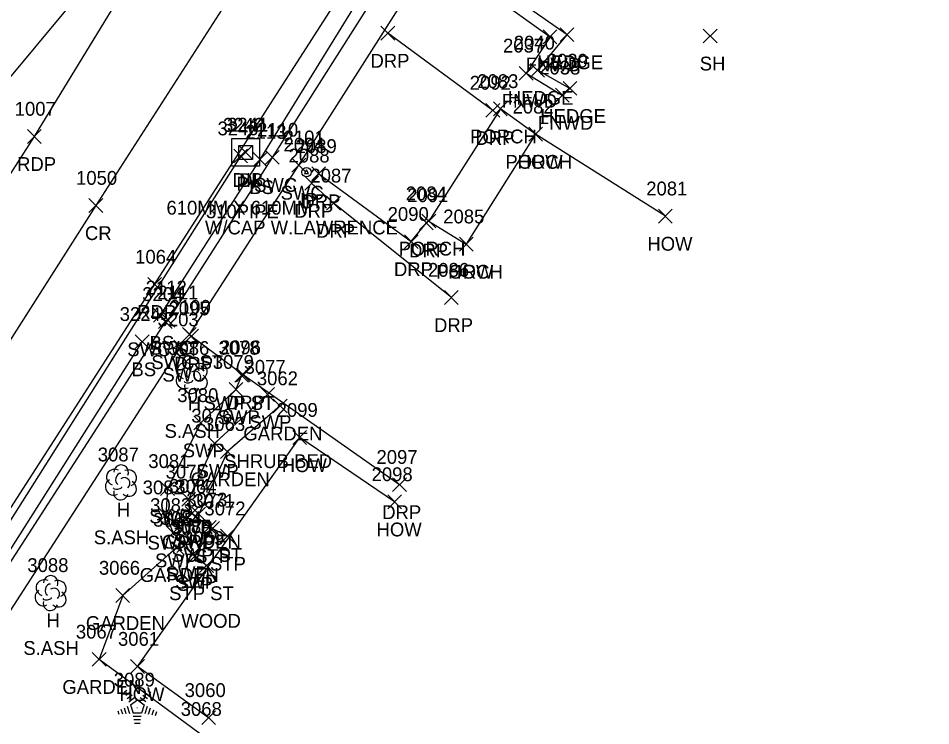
# Model space of a CAD drawing. Extents: x 1634209 to 1639641, y 608564 to 612258.
# Drawn here: x 1639021.2 to 1639153.3, y 611048.4 to 611150.8 of the extents above; entities that cross this region are included whole.
import ezdxf

# ---------------------------------------------------------------- set-up
doc = ezdxf.new("R2010")
doc.units = 0
for name, color, linetype in [('D_A', 7, 'Continuous'), ('D_C', 7, 'Continuous'), ('D_I', 7, 'Continuous'), ('D_TIC', 7, 'Continuous'), ('DCP', 7, 'Continuous'), ('DS', 7, 'Continuous'), ('L_A', 7, 'Continuous'), ('L_C', 7, 'Continuous'), ('L_I', 7, 'Continuous'), ('L_TIC', 7, 'Continuous'), ('LAHR', 7, 'Continuous'), ('LAPB', 7, 'Continuous'), ('LBC', 7, 'Continuous'), ('LBF', 7, 'Continuous'), ('LELB', 7, 'Continuous'), ('LFNC', 7, 'Continuous'), ('LTC', 7, 'Continuous'), ('LTD', 7, 'Continuous'), ('M_A', 7, 'Continuous'), ('M_C', 7, 'Continuous'), ('M_I', 7, 'Continuous'), ('MPIR', 7, 'Continuous'), ('P_A', 7, 'Continuous'), ('P_I', 7, 'Continuous'), ('P_TIC', 7, 'Continuous'), ('PET', 7, 'Continuous'), ('PRC', 7, 'Continuous'), ('R_A', 7, 'Continuous'), ('R_I', 7, 'Continuous'), ('R_TIC', 7, 'Continuous'), ('RDP', 7, 'Continuous'), ('RSW', 7, 'Continuous')]:
    doc.layers.add(name, color=color, linetype=linetype)

msp = doc.modelspace()

# ---------------------------------------------------------------- linework, layer by layer
at = {"layer": 'D_TIC'}
for points in [[(1639052.43, 611129.86), (1639054.43, 611131.86)], [(1639054.43, 611129.86), (1639052.43, 611131.86)], [(1639053.15, 611130.4), (1639055.15, 611132.4)], [(1639055.15, 611130.4), (1639053.15, 611132.4)]]:
    msp.add_lwpolyline(points, dxfattribs=at)
at = {"layer": 'DCP'}
msp.add_lwpolyline([(1638981.5, 611017.05), (1639053.43, 611130.86)], dxfattribs=at)
at = {"layer": 'DS'}
for p, q in [((1639052.14, 611133.38), (1639056.14, 611133.38)), ((1639052.14, 611129.38), (1639052.14, 611133.38)), ((1639056.14, 611133.38), (1639056.14, 611129.38)), ((1639053.14, 611130.38), (1639053.14, 611132.38)), ((1639053.14, 611132.38), (1639055.14, 611132.38)), ((1639055.14, 611132.38), (1639055.14, 611130.38)), ((1639055.14, 611130.38), (1639053.14, 611130.38)), ((1639054.14, 611131.38), (1639054.14, 611131.38)), ((1639054.14, 611131.38), (1639054.14, 611131.38)), ((1639056.14, 611129.38), (1639052.14, 611129.38))]:
    msp.add_line(p, q, dxfattribs=at)
at = {"layer": 'L_TIC'}
for points in [[(1639097.22, 611147.12), (1639099.22, 611149.12)], [(1639099.22, 611147.12), (1639097.22, 611149.12)], [(1639099.68, 611147.43), (1639101.68, 611149.43)], [(1639101.68, 611147.43), (1639099.68, 611149.43)], [(1639120.39, 611147.25), (1639122.39, 611149.25)], [(1639122.39, 611147.25), (1639120.39, 611149.25)], [(1639093.75, 611141.85), (1639095.75, 611143.85)], [(1639095.75, 611141.85), (1639093.75, 611143.85)], [(1639095.39, 611142.28), (1639097.39, 611144.28)], [(1639097.39, 611142.28), (1639095.39, 611144.28)], [(1639100.1, 611139.66), (1639102.1, 611141.66)], [(1639102.1, 611139.66), (1639100.1, 611141.66)], [(1639098.99, 611138.67), (1639100.99, 611140.67)], [(1639100.99, 611138.67), (1639098.99, 611140.67)], [(1639090.02, 611136.7), (1639092.02, 611138.7)], [(1639092.02, 611136.7), (1639090.02, 611138.7)], [(1639095.13, 611133.02), (1639097.13, 611135.02)], [(1639097.13, 611133.02), (1639095.13, 611135.02)], [(1639095.13, 611133.02), (1639097.13, 611135.02)], [(1639097.13, 611133.02), (1639095.13, 611135.02)], [(1639055.24, 611129.36), (1639057.24, 611131.36)], [(1639057.24, 611129.36), (1639055.24, 611131.36)], [(1639079.67, 611120.45), (1639081.67, 611122.45)], [(1639081.67, 611120.45), (1639079.67, 611122.45)], [(1639113.91, 611121.16), (1639115.91, 611123.16)], [(1639115.91, 611121.16), (1639113.91, 611123.16)], [(1639085.09, 611117.11), (1639087.09, 611119.11)], [(1639087.09, 611117.11), (1639085.09, 611119.11)], [(1639085.09, 611117.11), (1639087.09, 611119.11)], [(1639087.09, 611117.11), (1639085.09, 611119.11)], [(1639040.81, 611106.81), (1639042.81, 611108.81)], [(1639042.81, 611106.81), (1639040.81, 611108.81)], [(1639038.18, 611102.98), (1639040.18, 611104.98)], [(1639040.18, 611102.98), (1639038.18, 611104.98)], [(1639058.15, 611093.68), (1639060.15, 611095.68)], [(1639060.15, 611093.68), (1639058.15, 611095.68)], [(1639060.98, 611089.1), (1639062.98, 611091.1)], [(1639062.98, 611089.1), (1639060.98, 611091.1)], [(1639050.52, 611087.06), (1639052.52, 611089.06)], [(1639052.52, 611087.06), (1639050.52, 611089.06)], [(1639074.72, 611079.79), (1639076.72, 611081.79)], [(1639076.72, 611079.79), (1639074.72, 611081.79)], [(1639046.36, 611078.02), (1639048.36, 611080.02)], [(1639048.36, 611078.02), (1639046.36, 611080.02)], [(1639048.37, 611075.93), (1639050.37, 611077.93)], [(1639050.37, 611075.93), (1639048.37, 611077.93)], [(1639050.52, 611074.83), (1639052.52, 611076.83)], [(1639052.52, 611074.83), (1639050.52, 611076.83)], [(1639043.15, 611073.2), (1639045.15, 611075.2)], [(1639045.15, 611073.2), (1639043.15, 611075.2)], [(1639045.76, 611071.91), (1639047.76, 611073.91)], [(1639047.76, 611071.91), (1639045.76, 611073.91)], [(1639047.48, 611070.56), (1639049.48, 611072.56)], [(1639049.48, 611070.56), (1639047.48, 611072.56)], [(1639035.35, 611066.24), (1639037.35, 611068.24)], [(1639037.35, 611066.24), (1639035.35, 611068.24)], [(1639031.95, 611056.99), (1639033.95, 611058.99)], [(1639033.95, 611056.99), (1639031.95, 611058.99)], [(1639037.49, 611055.95), (1639039.49, 611057.95)], [(1639039.49, 611055.95), (1639037.49, 611057.95)], [(1639047.79, 611048.53), (1639049.79, 611050.53)], [(1639049.79, 611048.53), (1639047.79, 611050.53)]]:
    msp.add_lwpolyline(points, dxfattribs=at)
at = {"layer": 'LAHR'}
msp.add_lwpolyline([(1639101.1, 611140.66), (1639096.39, 611143.28), (1639100.68, 611148.43), (1639084.75, 611159.57), (1639110.62, 611199.46)], dxfattribs=at)
at = {"layer": 'LAPB'}
for points in [[(1639059.15, 611094.68), (1639051.52, 611088.06), (1639047.36, 611079.02)], [(1639044.15, 611074.2), (1639036.35, 611067.24), (1639032.95, 611057.99), (1639048.14, 611046.8)]]:
    msp.add_lwpolyline(points, dxfattribs=at)
at = {"layer": 'LBC'}
for points in [[(1639114.91, 611122.16), (1639096.13, 611134.02), (1639086.09, 611118.11)], [(1639038.49, 611056.95), (1639061.98, 611090.1)], [(1639075.72, 611080.79), (1639061.98, 611090.1)], [(1639048.79, 611049.53), (1639038.49, 611056.95)]]:
    msp.add_lwpolyline(points, dxfattribs=at)
at = {"layer": 'LBF'}
for points in [[(1639096.13, 611134.02), (1639091.02, 611137.7), (1639080.67, 611121.45), (1639086.09, 611118.11)], [(1639048.48, 611071.56), (1639046.76, 611072.91), (1639049.37, 611076.93), (1639051.52, 611075.83)]]:
    msp.add_lwpolyline(points, dxfattribs=at)
at = {"layer": 'LELB'}
for points in [[(1639041.81, 611107.81), (1639056.24, 611130.36), (1639075.11, 611161), (1639098.5, 611197.47), (1639122.91, 611234.07), (1639126.22, 611237.88)], [(1638966.07, 611052.28), (1638973.12, 611062.49), (1638979.47, 611078.29), (1638990.68, 611098.4), (1639000.87, 611114.56), (1639014.69, 611135.84), (1639038.15, 611164.03), (1639040.42, 611167.6)], [(1638982.99, 611014.59), (1639013.75, 611063.89), (1639039.18, 611103.98)]]:
    msp.add_lwpolyline(points, dxfattribs=at)
at = {"layer": 'LFNC'}
msp.add_lwpolyline([(1639109.56, 611199.9), (1639082.52, 611159.43), (1639098.22, 611148.12), (1639094.75, 611142.85), (1639099.99, 611139.67)], dxfattribs=at)
at = {"layer": 'LTC'}
for p, q in [((1639036.6, 611053.26), (1639036.96, 611053.52)), ((1639036.81, 611052.79), (1639037.34, 611053.18)), ((1639037.02, 611052.33), (1639037.73, 611052.84)), ((1639037.23, 611051.86), (1639038.11, 611052.5)), ((1639038.89, 611052.46), (1639039.7, 611051.87)), ((1639039.26, 611052.8), (1639039.94, 611052.31)), ((1639039.63, 611053.15), (1639040.18, 611052.75)), ((1639040, 611053.5), (1639040.42, 611053.2)), ((1639037, 611051.19), (1639037.33, 611050.17)), ((1639037.46, 611051.41), (1639038.47, 611052.14)), ((1639037.46, 611051.41), (1639037.85, 611050.21)), ((1639038.47, 611052.14), (1639039.47, 611051.42)), ((1639039.47, 611051.42), (1639039.08, 611050.21)), ((1639039.9, 611051.15), (1639039.57, 611050.11)), ((1639035.64, 611050.54), (1639035.79, 611050.07)), ((1639036.09, 611050.76), (1639036.3, 611050.1)), ((1639036.55, 611050.97), (1639036.82, 611050.14)), ((1639039.08, 611050.21), (1639037.85, 611050.21)), ((1639040.35, 611050.9), (1639040.06, 611050.01)), ((1639040.79, 611050.65), (1639040.56, 611049.92)), ((1639041.24, 611050.4), (1639041.05, 611049.82)), ((1639039.04, 611049.71), (1639037.89, 611049.71)), ((1639038.95, 611049.21), (1639037.97, 611049.21)), ((1639038.87, 611048.71), (1639038.04, 611048.71))]:
    msp.add_line(p, q, dxfattribs=at)
at = {"layer": 'LTD'}
for p, q in [((1639046.33, 611099.06), (1639046.33, 611099.06)), ((1639046.33, 611099.06), (1639046.33, 611099.06)), ((1639036.08, 611083.65), (1639036.08, 611083.65)), ((1639036.08, 611083.65), (1639036.08, 611083.65)), ((1639025.89, 611067.63), (1639025.89, 611067.63)), ((1639025.89, 611067.63), (1639025.89, 611067.63))]:
    msp.add_line(p, q, dxfattribs=at)
for centre in [(1639046.38, 611100.5), (1639036.13, 611085.09), (1639025.94, 611069.06)]:
    msp.add_arc(centre, 1.05, 335.5272, 180.9563, dxfattribs=at)
for centre, major_axis, ratio, start_param, end_param in [((1639045.54, 611099.73), (1.21, -0.51), 0.895232, 1.570796, 4.712389), ((1639046.12, 611099.52), (-0.208, -0.792), 0.645439, 3.141593, 6.283185), ((1639047.37, 611099.65), (-1.14, -0.48), 0.949671, 1.570796, 4.712389), ((1639045.25, 611098.36), (0.58, -1.04), 0.959034, 3.141593, 6.283185), ((1639046.83, 611098.9), (-0.5, 0.667), 0.989748, 3.141593, 6.283185), ((1639047.33, 611098.23), (-1.09, 0.79), 0.841452, 1.570796, 4.712389), ((1639046.33, 611097.56), (0.26, 1.06), 0.942809, 1.570796, 4.712389), ((1639045.87, 611098.31), (-0.625, -0.083), 0.423636, 0, 3.141593), ((1639035.29, 611084.32), (1.21, -0.51), 0.895232, 1.570796, 4.712389), ((1639037.12, 611084.23), (-1.14, -0.48), 0.949671, 1.570796, 4.712389), ((1639035.87, 611084.11), (-0.208, -0.792), 0.645439, 3.141593, 6.283185), ((1639036.58, 611083.48), (-0.5, 0.667), 0.989748, 3.141593, 6.283185), ((1639035, 611082.94), (0.58, -1.04), 0.959034, 3.141593, 6.283185), ((1639035.62, 611082.9), (-0.625, -0.083), 0.423636, 0, 3.141593), ((1639037.08, 611082.82), (-1.09, 0.79), 0.841452, 1.570796, 4.712389), ((1639036.08, 611082.15), (0.26, 1.06), 0.942809, 1.570796, 4.712389), ((1639025.1, 611068.3), (1.21, -0.51), 0.895232, 1.570796, 4.712389), ((1639025.68, 611068.09), (-0.208, -0.792), 0.645439, 3.141593, 6.283185), ((1639026.39, 611067.46), (-0.5, 0.667), 0.989748, 3.141593, 6.283185), ((1639026.93, 611068.21), (-1.14, -0.48), 0.949671, 1.570796, 4.712389), ((1639024.81, 611066.92), (0.58, -1.04), 0.959034, 3.141593, 6.283185), ((1639025.43, 611066.88), (-0.625, -0.083), 0.423636, 0, 3.141593), ((1639026.89, 611066.8), (-1.09, 0.79), 0.841452, 1.570796, 4.712389), ((1639025.89, 611066.13), (0.26, 1.06), 0.942809, 1.570796, 4.712389)]:
    msp.add_ellipse(centre, major_axis=major_axis, ratio=ratio, start_param=start_param, end_param=end_param, dxfattribs=at)
at = {"layer": 'MPIR'}
msp.add_lwpolyline([(1639062.96, 611128.85), (1639062.68, 611128.35), (1639063.25, 611128.35)], close=True, dxfattribs=at)
msp.add_circle((1639062.96, 611128.52), 0.667, dxfattribs=at)
at = {"layer": 'P_TIC'}
for points in [[(1639022.57, 611132.7), (1639024.57, 611134.7)], [(1639024.57, 611132.7), (1639022.57, 611134.7)], [(1639031.46, 611122.7), (1639033.46, 611124.7)], [(1639033.46, 611122.7), (1639031.46, 611124.7)], [(1639039.97, 611111.28), (1639041.97, 611113.28)], [(1639041.97, 611111.28), (1639039.97, 611113.28)]]:
    msp.add_lwpolyline(points, dxfattribs=at)
at = {"layer": 'PET'}
for points in [[(1638854.83, 610853.22), (1638885.37, 610909), (1638902.82, 610937.28), (1638929.33, 610982.56), (1638950.92, 611019.42), (1638971.29, 611051.92), (1639000.04, 611096.96), (1639023.57, 611133.7), (1639039.12, 611159.19), (1639064.62, 611197.78), (1639080.51, 611223.3), (1639114.23, 611277.34), (1639131.17, 611302.28), (1639149.64, 611331.79), (1639176.42, 611372.35), (1639193.48, 611398.88), (1639220.96, 611441.47), (1639247.22, 611483.75)], [(1638878.4, 610839.82), (1638902.26, 610883.1), (1638925.76, 610925.06), (1638957.25, 610978.12), (1638978.73, 611014.12), (1639004.29, 611055.32), (1639040.97, 611112.28), (1639073.41, 611162.89), (1639072.72, 611163.46), (1639102.57, 611207.56), (1639124.27, 611240.99), (1639140.69, 611264.29), (1639156.2, 611287.4), (1639175.63, 611318.1), (1639189.77, 611341.61), (1639219.88, 611389.38), (1639245.26, 611428.04), (1639265.27, 611462.65)]]:
    msp.add_lwpolyline(points, dxfattribs=at)
at = {"layer": 'PRC'}
msp.add_lwpolyline([(1639250.46, 611462.84), (1639222.36, 611418.18), (1639195.34, 611376.28), (1639169.71, 611336.75), (1639147.17, 611302.78), (1639120.59, 611261.16), (1639092.55, 611217.83), (1639063.71, 611172.41), (1639032.46, 611123.7), (1639004.79, 611080.3), (1638977.88, 611037.27), (1638950.44, 610992.13), (1638925.96, 610950.29), (1638900.29, 610905.36), (1638879.75, 610869.2), (1638867.15, 610846.08)], dxfattribs=at)
at = {"layer": 'R_TIC'}
for points in [[(1639073.73, 611147.65), (1639075.73, 611149.65)], [(1639075.73, 611147.65), (1639073.73, 611149.65)], [(1639088.93, 611136.47), (1639090.93, 611138.47)], [(1639090.93, 611136.47), (1639088.93, 611138.47)], [(1639057.01, 611129.67), (1639059.01, 611131.67)], [(1639059.01, 611129.67), (1639057.01, 611131.67)], [(1639060.85, 611128.55), (1639062.85, 611130.55)], [(1639062.85, 611128.55), (1639060.85, 611130.55)], [(1639063.73, 611127.3), (1639065.73, 611129.3)], [(1639065.73, 611127.3), (1639063.73, 611129.3)], [(1639062.7, 611125.93), (1639064.7, 611127.93)], [(1639064.7, 611125.93), (1639062.7, 611127.93)], [(1639065.86, 611123.03), (1639067.86, 611125.03)], [(1639067.86, 611123.03), (1639065.86, 611125.03)], [(1639079.31, 611120.19), (1639081.31, 611122.19)], [(1639081.31, 611120.19), (1639079.31, 611122.19)], [(1639077.13, 611117.47), (1639079.13, 611119.47)], [(1639079.13, 611117.47), (1639077.13, 611119.47)], [(1639082.93, 611109.38), (1639084.93, 611111.38)], [(1639084.93, 611109.38), (1639082.93, 611111.38)], [(1639041.92, 611106.1), (1639043.92, 611108.1)], [(1639043.92, 611106.1), (1639041.92, 611108.1)], [(1639041.52, 611105.87), (1639043.52, 611107.87)], [(1639043.52, 611105.87), (1639041.52, 611107.87)], [(1639045.01, 611104.02), (1639047.01, 611106.02)], [(1639047.01, 611104.02), (1639045.01, 611106.02)], [(1639045.32, 611103.8), (1639047.32, 611105.8)], [(1639047.32, 611103.8), (1639045.32, 611105.8)], [(1639043.74, 611102.21), (1639045.74, 611104.21)], [(1639045.74, 611102.21), (1639043.74, 611104.21)], [(1639052.56, 611098.1), (1639054.56, 611100.1)], [(1639054.56, 611098.1), (1639052.56, 611100.1)], [(1639052.82, 611098.17), (1639054.82, 611100.17)], [(1639054.82, 611098.17), (1639052.82, 611100.17)], [(1639051.74, 611096.05), (1639053.74, 611098.05)], [(1639053.74, 611096.05), (1639051.74, 611098.05)], [(1639056.33, 611095.34), (1639058.33, 611097.34)], [(1639058.33, 611095.34), (1639056.33, 611097.34)], [(1639046.67, 611091.24), (1639048.67, 611093.24)], [(1639048.67, 611091.24), (1639046.67, 611093.24)], [(1639048.68, 611088.27), (1639050.68, 611090.27)], [(1639050.68, 611088.27), (1639048.68, 611090.27)], [(1639075.43, 611082.29), (1639077.43, 611084.29)], [(1639077.43, 611082.29), (1639075.43, 611084.29)], [(1639041.84, 611081.69), (1639043.84, 611083.69)], [(1639043.84, 611081.69), (1639041.84, 611083.69)], [(1639044.91, 611080.16), (1639046.91, 611082.16)], [(1639046.91, 611080.16), (1639044.91, 611082.16)], [(1639041.59, 611077.88), (1639043.59, 611079.88)], [(1639043.59, 611077.88), (1639041.59, 611079.88)], [(1639045.39, 611078.1), (1639047.39, 611080.1)], [(1639047.39, 611078.1), (1639045.39, 611080.1)], [(1639047.89, 611076.11), (1639049.89, 611078.11)], [(1639049.89, 611076.11), (1639047.89, 611078.11)], [(1639042.66, 611075.31), (1639044.66, 611077.31)], [(1639044.66, 611075.31), (1639042.66, 611077.31)], [(1639044.19, 611073.44), (1639046.19, 611075.44)], [(1639046.19, 611073.44), (1639044.19, 611075.44)], [(1639045.58, 611072.23), (1639047.58, 611074.23)], [(1639047.58, 611072.23), (1639045.58, 611074.23)]]:
    msp.add_lwpolyline(points, dxfattribs=at)
at = {"layer": 'RDP'}
for points in [[(1639089.93, 611137.47), (1639074.73, 611148.65)], [(1639083.93, 611110.38), (1639066.86, 611124.03), (1639063.7, 611126.93), (1639064.73, 611128.3), (1639078.13, 611118.47), (1639080.31, 611121.19)], [(1639046.32, 611104.8), (1639053.82, 611099.17), (1639076.43, 611083.29)]]:
    msp.add_lwpolyline(points, dxfattribs=at)
at = {"layer": 'RSW'}
for points in [[(1639046.01, 611105.02), (1639061.85, 611129.55), (1639078.57, 611155.9), (1639101.99, 611191.52), (1639128.62, 611231.94), (1639130.78, 611235.12), (1639127.67, 611237.28), (1639125.39, 611233.9), (1639098.32, 611192.86), (1639074.54, 611156.78), (1639058.01, 611130.67), (1639042.92, 611107.1)], [(1639042.52, 611106.87), (1639016.95, 611067.31), (1638996.03, 611033.02), (1638978.68, 611004.78), (1638963.33, 610979.05), (1638946.23, 610950.27), (1638931.64, 610924.09), (1638919.4, 610902.22), (1638904.83, 610875.98), (1638895.3, 610858.44), (1638883.54, 610836.57)], [(1638887.24, 610836.54), (1638902.8, 610864.3), (1638908.08, 610874.62), (1638910.81, 610879.12), (1638923.92, 610902.1), (1638938.05, 610928.02), (1638949.86, 610948.73), (1638968.01, 610979.25), (1638983.29, 611004.79), (1638997.34, 611027.92), (1639015.73, 611058.3), (1639044.74, 611103.21)], [(1639053.56, 611099.1), (1639052.74, 611097.05), (1639047.67, 611092.24), (1639042.84, 611082.69), (1639042.59, 611078.88), (1639043.66, 611076.31), (1639045.19, 611074.44), (1639046.58, 611073.23)], [(1639048.89, 611077.11), (1639046.39, 611079.1), (1639045.91, 611081.16), (1639049.68, 611089.27), (1639057.33, 611096.34)]]:
    msp.add_lwpolyline(points, dxfattribs=at)

# ---------------------------------------------------------------- texts
at = {"layer": 'D_A'}
for s, p in [('DIB', (1639052.25, 611126.4)), ('P', (1639052.8, 611125.86)), ('DI', (1639053.2, 611126.38))]:
    msp.add_text(s, height=2, dxfattribs=at).set_placement(p)
at = {"layer": 'D_C'}
for s, p in [('610MM X 610MM', (1639042.69, 611122.38)), ('310PIPE', (1639048.39, 611121.86))]:
    msp.add_text(s, height=2, dxfattribs=at).set_placement(p)
at = {"layer": 'D_I'}
for s, p in [('3240', (1639050.08, 611133.86)), ('3242', (1639050.88, 611134.38)), ('3241', (1639051.46, 611134.4))]:
    msp.add_text(s, height=2, dxfattribs=at).set_placement(p)
at = {"layer": 'L_A'}
for s, p in [('FNWD', (1639094.69, 611143.12)), ('HEDGE', (1639096.38, 611143.43)), ('SH', (1639119.88, 611143.25)), ('FNWD', (1639091.22, 611137.85)), ('HEDGE', (1639092.09, 611138.28)), ('HEDGE', (1639096.8, 611135.66)), ('FNWD', (1639096.46, 611134.67)), ('PORCH', (1639086.64, 611132.7)), ('PORCH', (1639091.75, 611129.02)), ('HOW', (1639093.51, 611129.02)), ('BS', (1639054.68, 611125.36)), ('PORCH', (1639076.3, 611116.45)), ('HOW', (1639112.3, 611117.16)), ('PORCH', (1639081.72, 611113.11)), ('HOW', (1639083.48, 611113.11)), ('BS', (1639040.25, 611102.81)), ('BS', (1639037.62, 611098.98)), ('H', (1639045.76, 611094.06)), ('GARDEN', (1639053.82, 611089.68)), ('HOW', (1639059.37, 611085.1)), ('GARDEN', (1639046.19, 611083.06)), ('H', (1639035.51, 611078.65)), ('HOW', (1639073.1, 611075.79)), ('GARDEN', (1639042.03, 611074.02)), ('STP', (1639046.83, 611071.93)), ('STP', (1639048.98, 611070.83)), ('GARDEN', (1639038.82, 611069.2)), ('STP', (1639044.22, 611067.91)), ('STP ST', (1639043.07, 611066.56)), ('H', (1639025.32, 611062.63)), ('GARDEN', (1639031.02, 611062.24)), ('GARDEN', (1639027.62, 611052.99)), ('HOW', (1639035.87, 611051.95))]:
    msp.add_text(s, height=2, dxfattribs=at).set_placement(p)
at = {"layer": 'L_C'}
for s, p in [('S.ASH', (1639042.41, 611090.06)), ('SHRUB BED', (1639051.05, 611085.68)), ('S.ASH', (1639032.16, 611074.65)), ('WOOD', (1639044.84, 611062.56)), ('S.ASH', (1639021.97, 611058.63))]:
    msp.add_text(s, height=2, dxfattribs=at).set_placement(p)
at = {"layer": 'L_I'}
for s, p in [('2037', (1639091.41, 611145.85)), ('2040', (1639092.96, 611146.28)), ('2039', (1639097.75, 611143.66)), ('2038', (1639096.65, 611142.67)), ('2083', (1639087.68, 611140.7)), ('2082', (1639092.79, 611137.02)), ('2082', (1639092.79, 611137.02)), ('2113', (1639054.11, 611133.36)), ('2084', (1639077.33, 611124.45)), ('2081', (1639112.14, 611125.16)), ('2085', (1639082.75, 611121.11)), ('2085', (1639082.75, 611121.11)), ('2112', (1639039.68, 611110.81)), ('3224', (1639035.92, 611106.98)), ('3086', (1639042.94, 611102.06)), ('3062', (1639055.77, 611097.68)), ('2099', (1639058.64, 611093.1)), ('3063', (1639048.13, 611091.06)), ('3087', (1639032.74, 611086.65)), ('2098', (1639072.38, 611083.79)), ('3064', (1639043.97, 611082.02)), ('3071', (1639046.6, 611079.93)), ('3072', (1639048.18, 611078.83)), ('3065', (1639040.76, 611077.2)), ('3070', (1639043.34, 611075.91)), ('3069', (1639045.09, 611074.56)), ('3088', (1639022.55, 611070.63)), ('3066', (1639032.91, 611070.24)), ('3067', (1639029.57, 611060.99)), ('3061', (1639035.67, 611059.95)), ('3089', (1639035.06, 611054.05)), ('3060', (1639045.32, 611052.53)), ('3068', (1639044.75, 611049.8))]:
    msp.add_text(s, height=2, dxfattribs=at).set_placement(p)
at = {"layer": 'LTC'}
msp.add_text('.', height=1.04, rotation=270, dxfattribs=at).set_placement((1639038.35, 611051.16))
at = {"layer": 'M_A'}
msp.add_text('IP', height=2, dxfattribs=at).set_placement((1639062.01, 611123.52))
at = {"layer": 'M_C'}
msp.add_text('W/CAP W.LAWRENCE', height=2, dxfattribs=at).set_placement((1639048.26, 611119.52))
at = {"layer": 'M_I'}
msp.add_text('2094', height=2, dxfattribs=at).set_placement((1639059.63, 611131.52))
at = {"layer": 'P_A'}
for s, p in [('RDP', (1639021.06, 611128.7)), ('CR', (1639030.89, 611118.7)), ('RDP', (1639038.45, 611107.28))]:
    msp.add_text(s, height=2, dxfattribs=at).set_placement(p)
at = {"layer": 'P_I'}
for s, p in [('1007', (1639020.72, 611136.7)), ('1050', (1639029.6, 611126.7)), ('1064', (1639038.15, 611115.28))]:
    msp.add_text(s, height=2, dxfattribs=at).set_placement(p)
at = {"layer": 'R_A'}
for s, p in [('DRP', (1639072.22, 611143.65)), ('DRP', (1639087.42, 611132.47)), ('SWC', (1639055.37, 611125.67)), ('SWC', (1639059.21, 611124.55)), ('DRP', (1639062.22, 611123.3)), ('DRP', (1639061.19, 611121.93)), ('DRP', (1639064.35, 611119.03)), ('DRP', (1639077.8, 611116.19)), ('DRP', (1639075.62, 611113.47)), ('DRP', (1639081.42, 611105.38)), ('SWC', (1639040.29, 611102.1)), ('SWC ST', (1639037.01, 611101.87)), ('SWC ST', (1639040.5, 611100.02)), ('DRP', (1639043.8, 611099.8)), ('SWC', (1639042.1, 611098.21)), ('SWP ST', (1639048.05, 611094.1)), ('DRP', (1639051.31, 611094.17)), ('SWP', (1639050.1, 611092.05)), ('SWP', (1639054.69, 611091.34)), ('SWP', (1639045.04, 611087.24)), ('SWP', (1639047.05, 611084.27)), ('DRP', (1639073.92, 611078.29)), ('SWP', (1639040.2, 611077.69)), ('SWP', (1639043.27, 611076.16)), ('SWP', (1639039.95, 611073.88)), ('SWP', (1639043.75, 611074.1)), ('SWP ST', (1639043.39, 611072.11)), ('SWP', (1639041.03, 611071.31)), ('SWP', (1639042.56, 611069.44)), ('SWP', (1639043.94, 611068.23))]:
    msp.add_text(s, height=2, dxfattribs=at).set_placement(p)
at = {"layer": 'R_I'}
for s, p in [('2092', (1639086.59, 611140.47)), ('2110', (1639055.8, 611133.67)), ('2101', (1639059.65, 611132.55)), ('2089', (1639061.39, 611131.3)), ('2088', (1639060.36, 611129.93)), ('2087', (1639063.52, 611127.03)), ('2091', (1639077.54, 611124.19)), ('2090', (1639074.71, 611121.47)), ('2086', (1639080.54, 611113.38)), ('3204', (1639039.18, 611109.87)), ('2111', (1639041.36, 611110.1)), ('2095', (1639042.98, 611107.8)), ('2100', (1639043.15, 611108.02)), ('3203', (1639041.4, 611106.21)), ('3078', (1639050.22, 611102.1)), ('2096', (1639050.42, 611102.17)), ('3079', (1639049.39, 611100.05)), ('3077', (1639053.99, 611099.34)), ('3080', (1639044.25, 611095.24)), ('3076', (1639046.29, 611092.27)), ('2097', (1639073.09, 611086.29)), ('3081', (1639040.06, 611085.69)), ('3075', (1639042.57, 611084.16)), ('3074', (1639043.05, 611082.1)), ('3082', (1639039.25, 611081.88)), ('3073', (1639045.55, 611080.11)), ('3083', (1639040.32, 611079.31)), ('3084', (1639041.86, 611077.44)), ('3085', (1639043.24, 611076.23))]:
    msp.add_text(s, height=2, dxfattribs=at).set_placement(p)

doc.saveas('drawing.dxf')
